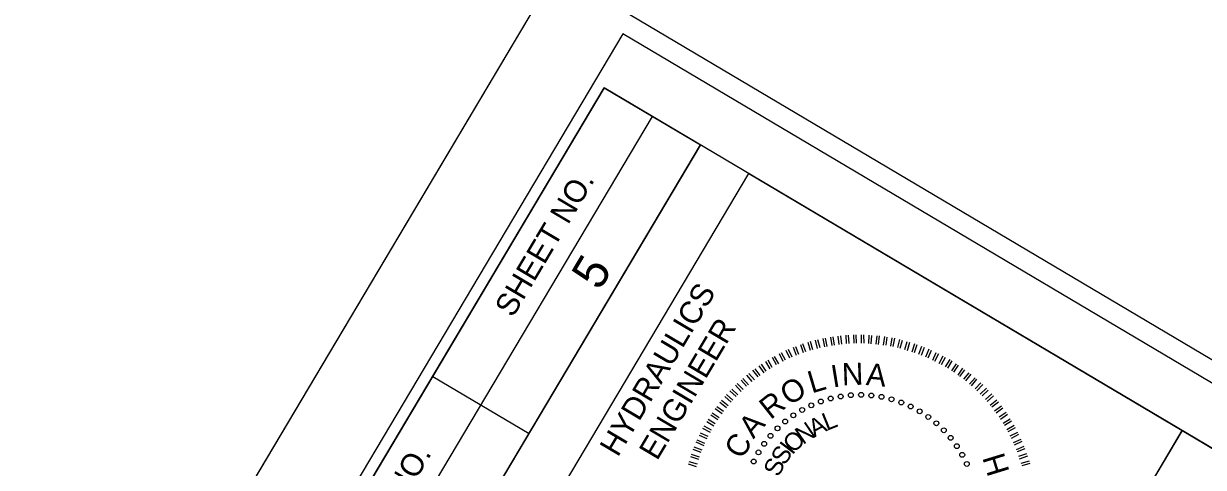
# Model space of a CAD drawing. Extents: x 2138768 to 2143723, y 406633 to 414335.
# Drawn here: x 2141672.7 to 2141936, y 412134 to 412233.2 of the extents above; entities that cross this region are included whole.
import ezdxf

# ---------------------------------------------------------------- set-up
doc = ezdxf.new("R2010")
doc.units = 0
for name, color, linetype in [('Sheet Cutting Line CELL', 7, 'Continuous'), ('Sheet Data Field CELL', 7, 'Continuous'), ('Sheet Plan And Profile CELL', 7, 'Continuous'), ('Sheet Plot Border Inside CELL', 7, 'Continuous'), ('Sheet Plot Border Outside CELL', 7, 'Continuous'), ('Sheet Sticker Exception Certification CELL', 7, 'Continuous'), ('Sheet Sticker Preliminary CELL', 7, 'Continuous')]:
    doc.layers.add(name, color=color, linetype=linetype)

msp = doc.modelspace()

# ---------------------------------------------------------------- linework, layer by layer
at = {"layer": 'Sheet Cutting Line CELL'}
msp.add_line((2141791.54, 412244.96), (2140932.27, 410797.26), dxfattribs=at)
at = {"layer": 'Sheet Plan And Profile CELL'}
for p, q in [((2141710.89, 412040.42), (2141813, 412212.45)), ((2141721.64, 412034.04), (2141823.75, 412206.07)), ((2141763.97, 412154.33), (2141785.47, 412141.57))]:
    msp.add_line(p, q, dxfattribs=at)
for points in [[(2141802.21, 412218.85), (2141036.6, 410928.95), (2141939.53, 410393.03), (2142705.14, 411682.93)], [(2141700.1, 412046.82), (2141802.21, 412218.85), (2141823.75, 412206.07), (2141721.64, 412034.04)], [(2141783.46, 412113.69), (2141834.5, 412199.69), (2141931.24, 412142.27), (2141880.2, 412056.27)]]:
    msp.add_lwpolyline(points, close=True, dxfattribs=at)
at = {"layer": 'Sheet Plot Border Inside CELL'}
msp.add_lwpolyline([(2141863.34, 410259.75), (2142713.67, 411692.4), (2141806.44, 412230.88), (2140956.1, 410798.23)], close=True, dxfattribs=at)
at = {"layer": 'Sheet Plot Border Outside CELL'}
msp.add_lwpolyline([(2141873.9, 410238.36), (2142733.16, 411686.06), (2141791.54, 412244.96), (2140932.27, 410797.26)], close=True, dxfattribs=at)
at = {"layer": 'Sheet Sticker Exception Certification CELL'}
for p, q in [((2141829.13, 411970.24), (2141931.23, 412142.26)), ((2141931.24, 412142.25), (2141951.45, 412130.26))]:
    msp.add_line(p, q, dxfattribs=at)
at = {"layer": 'Sheet Sticker Preliminary CELL'}
for p, q in [((2141848.27, 412160.11), (2141847.74, 412161.93)), ((2141848.82, 412160.29), (2141848.25, 412162.13)), ((2141849.86, 412160.62), (2141849.36, 412162.42)), ((2141850.42, 412160.73), (2141849.93, 412162.53)), ((2141851.45, 412160.96), (2141851.09, 412162.79)), ((2141852.02, 412161.07), (2141851.61, 412162.92)), ((2141853.08, 412161.27), (2141852.79, 412163.12)), ((2141853.62, 412161.34), (2141853.33, 412163.18)), ((2141854.71, 412161.47), (2141854.48, 412163.34)), ((2141855.25, 412161.54), (2141855.04, 412163.45)), ((2141856.33, 412161.68), (2141856.21, 412163.54)), ((2141856.89, 412161.68), (2141856.75, 412163.6)), ((2141857.99, 412161.75), (2141857.94, 412163.63)), ((2141858.55, 412161.76), (2141858.49, 412163.63)), ((2141859.63, 412161.79), (2141859.68, 412163.65)), ((2141860.23, 412161.76), (2141860.21, 412163.61)), ((2141861.3, 412161.69), (2141861.37, 412163.59)), ((2141861.83, 412161.65), (2141861.95, 412163.53)), ((2141862.9, 412161.57), (2141863.12, 412163.45)), ((2141863.48, 412161.51), (2141863.66, 412163.41)), ((2141864.56, 412161.36), (2141864.85, 412163.26)), ((2141865.14, 412161.3), (2141865.4, 412163.15)), ((2141866.2, 412161.12), (2141866.53, 412162.98)), ((2141866.75, 412161.01), (2141867.08, 412162.88)), ((2141867.78, 412160.79), (2141868.24, 412162.58)), ((2141868.31, 412160.64), (2141868.79, 412162.48)), ((2141869.36, 412160.35), (2141869.88, 412162.16)), ((2141869.93, 412160.18), (2141870.41, 412162.02)), ((2141842.17, 412157.72), (2141841.33, 412159.39)), ((2141842.7, 412157.96), (2141841.82, 412159.65)), ((2141843.64, 412158.41), (2141842.88, 412160.14)), ((2141844.17, 412158.65), (2141843.39, 412160.34)), ((2141845.19, 412159.05), (2141844.46, 412160.82)), ((2141845.7, 412159.25), (2141845.01, 412160.99)), ((2141846.71, 412159.64), (2141846.09, 412161.41)), ((2141847.26, 412159.82), (2141846.6, 412161.61)), ((2141870.96, 412159.85), (2141871.54, 412161.68)), ((2141871.49, 412159.71), (2141872.09, 412161.47)), ((2141872.49, 412159.33), (2141873.16, 412161.11)), ((2141873.04, 412159.12), (2141873.7, 412160.9)), ((2141874.04, 412158.75), (2141874.79, 412160.48)), ((2141874.56, 412158.5), (2141875.31, 412160.22)), ((2141875.55, 412158.02), (2141876.34, 412159.72)), ((2141876.03, 412157.79), (2141876.89, 412159.51)), ((2141837.93, 412155.17), (2141836.86, 412156.75)), ((2141838.4, 412155.5), (2141837.33, 412157.08)), ((2141839.3, 412156.08), (2141838.3, 412157.67)), ((2141839.75, 412156.37), (2141838.82, 412157.98)), ((2141840.7, 412156.92), (2141839.78, 412158.58)), ((2141841.19, 412157.19), (2141840.28, 412158.84)), ((2141877, 412157.27), (2141877.9, 412158.96)), ((2141877.52, 412157.01), (2141878.39, 412158.67)), ((2141878.43, 412156.48), (2141879.41, 412158.12)), ((2141878.92, 412156.18), (2141879.9, 412157.83)), ((2141879.81, 412155.6), (2141880.87, 412157.2)), ((2141880.3, 412155.31), (2141881.34, 412156.87)), ((2141834.45, 412152.5), (2141833.18, 412153.92)), ((2141835.27, 412153.23), (2141834.07, 412154.67)), ((2141835.75, 412153.56), (2141834.54, 412155)), ((2141836.59, 412154.23), (2141835.43, 412155.75)), ((2141837.03, 412154.59), (2141835.91, 412156.08)), ((2141881.2, 412154.67), (2141882.28, 412156.2)), ((2141881.63, 412154.36), (2141882.75, 412155.86)), ((2141882.53, 412153.71), (2141883.69, 412155.19)), ((2141882.97, 412153.33), (2141884.13, 412154.82)), ((2141883.78, 412152.63), (2141885.02, 412154.07)), ((2141832.05, 412150.24), (2141830.71, 412151.54)), ((2141832.84, 412151), (2141831.54, 412152.38)), ((2141833.25, 412151.42), (2141831.93, 412152.76)), ((2141834.01, 412152.14), (2141832.78, 412153.54)), ((2141884.19, 412152.28), (2141885.43, 412153.72)), ((2141885.03, 412151.55), (2141886.29, 412152.92)), ((2141885.41, 412151.16), (2141886.74, 412152.55)), ((2141886.17, 412150.38), (2141887.54, 412151.74)), ((2141886.55, 412149.98), (2141887.94, 412151.28)), ((2141829.88, 412147.8), (2141828.39, 412148.96)), ((2141830.58, 412148.61), (2141829.14, 412149.85)), ((2141830.96, 412149.05), (2141829.52, 412150.29)), ((2141831.7, 412149.84), (2141830.31, 412151.16)), ((2141887.31, 412149.2), (2141888.71, 412150.43)), ((2141887.67, 412148.76), (2141889.09, 412150.04)), ((2141888.36, 412147.96), (2141889.85, 412149.14)), ((2141888.72, 412147.53), (2141890.2, 412148.71)), ((2141827.9, 412145.13), (2141826.34, 412146.16)), ((2141828.55, 412146.02), (2141827.01, 412147.1)), ((2141828.88, 412146.49), (2141827.35, 412147.57)), ((2141829.54, 412147.33), (2141828.06, 412148.49)), ((2141889.36, 412146.64), (2141890.93, 412147.78)), ((2141889.72, 412146.21), (2141891.22, 412147.33)), ((2141890.36, 412145.33), (2141891.92, 412146.35)), ((2141826.74, 412143.26), (2141825.13, 412144.21)), ((2141827.03, 412143.75), (2141825.42, 412144.7)), ((2141827.63, 412144.67), (2141826.03, 412145.73)), ((2141890.67, 412144.81), (2141892.21, 412145.9)), ((2141891.25, 412143.91), (2141892.85, 412144.91)), ((2141891.54, 412143.46), (2141893.14, 412144.46)), ((2141892.1, 412142.52), (2141893.71, 412143.45)), ((2141825.2, 412140.38), (2141823.49, 412141.17)), ((2141825.45, 412140.9), (2141823.74, 412141.69)), ((2141825.94, 412141.83), (2141824.25, 412142.73)), ((2141826.2, 412142.35), (2141824.54, 412143.22)), ((2141892.36, 412142.02), (2141894.02, 412142.94)), ((2141892.85, 412141.06), (2141894.52, 412141.91)), ((2141893.12, 412140.57), (2141894.79, 412141.42)), ((2141824.09, 412137.86), (2141822.34, 412138.57)), ((2141824.53, 412138.88), (2141822.8, 412139.63)), ((2141824.72, 412139.38), (2141822.99, 412140.13)), ((2141893.58, 412139.57), (2141895.27, 412140.35)), ((2141893.78, 412139.06), (2141895.53, 412139.86)), ((2141894.24, 412138.06), (2141895.99, 412138.75)), ((2141894.44, 412137.56), (2141896.19, 412138.25)), ((2141823.36, 412135.79), (2141821.56, 412136.41)), ((2141823.51, 412136.31), (2141821.74, 412136.91)), ((2141823.9, 412137.36), (2141822.13, 412138.02)), ((2141894.78, 412136.52), (2141896.58, 412137.12)), ((2141894.95, 412135.97), (2141896.78, 412136.61)), ((2141895.31, 412134.98), (2141897.13, 412135.51)), ((2141822.86, 412134.19), (2141821.07, 412134.75)), ((2141823.03, 412134.76), (2141821.22, 412135.28)), ((2141895.49, 412134.43), (2141897.27, 412134.99))]:
    msp.add_line(p, q, dxfattribs=at)
for centre in [(2141850.58, 412148.75), (2141852.77, 412149.42), (2141855.01, 412149.88), (2141857.28, 412150.16), (2141859.57, 412150.23), (2141861.86, 412150.1), (2141864.12, 412149.78), (2141866.35, 412149.25), (2141868.53, 412148.54), (2141844.46, 412145.66), (2141846.41, 412146.87), (2141848.45, 412147.9), (2141870.63, 412147.64), (2141872.65, 412146.56), (2141842.63, 412144.29), (2141874.56, 412145.3), (2141876.36, 412143.89), (2141839.36, 412141.09), (2141840.92, 412142.76), (2141878.03, 412142.32), (2141879.56, 412140.62), (2141837.94, 412139.29), (2141880.93, 412138.78), (2141835.61, 412135.36), (2141836.69, 412137.38), (2141882.14, 412136.84), (2141883.17, 412134.8)]:
    msp.add_circle(centre, 0.543, dxfattribs=at)

# ---------------------------------------------------------------- texts
at = {"layer": 'Sheet Data Field CELL'}
msp.add_text('5', height=7.75, rotation=59.3093, dxfattribs=at).set_placement((2141801.23, 412173.31))
at = {"layer": 'Sheet Plan And Profile CELL'}
for s, height, p in [('SHEET NO.', 5, (2141781.86, 412167.32)), ('HYDRAULICS', 5, (2141805.28, 412136.15)), ('ENGINEER', 5, (2141814.05, 412135.36)), ('PROJECT REFERENCE NO.', 5.0001, (2141718.91, 412061.47))]:
    msp.add_text(s, height=height, rotation=59.3093, dxfattribs=at).set_placement(p)
at = {"layer": 'Sheet Sticker Preliminary CELL'}
for s, height, rotation, p in [('I', 4.96, 9.2695, (2141853.28, 412151.85)), ('N', 4.96, 2.004, (2141855.36, 412152.34)), ('A', 4.96, 354.7385, (2141860.54, 412152.44)), ('L', 4.96, 16.535, (2141848.55, 412150.53)), ('O', 4.96, 31.066, (2141843.43, 412147.72)), ('R', 4.96, 38.3315, (2141839.37, 412144.56)), ('L', 3.98, 21.8725, (2141851.88, 412142.15)), ('A', 4.96, 49.0114, (2141835.54, 412140.26)), ('N', 3.98, 34.2403, (2141846.6, 412138.99)), ('A', 3.98, 28.0564, (2141849.15, 412140.65)), ('C', 4.96, 60.128, (2141833.08, 412135.64)), ('O', 3.98, 46.6081, (2141844.59, 412137.01)), ('S', 3.98, 58.9759, (2141842.59, 412134.29)), ('I', 3.98, 52.792, (2141844.26, 412136.64)), ('S', 3.98, 65.1598, (2141841.22, 412131.71)), ('H', 4.98, 107.0795, (2141892.74, 412133.09))]:
    msp.add_text(s, height=height, rotation=rotation, dxfattribs=at).set_placement(p)

doc.saveas('drawing.dxf')
